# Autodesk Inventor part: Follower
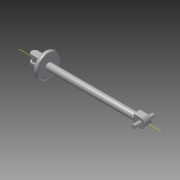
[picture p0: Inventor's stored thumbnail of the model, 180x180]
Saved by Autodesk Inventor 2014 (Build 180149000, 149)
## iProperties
Created: 2008-06
Part Number: Follower
Document SubType Name: Modeling
Designer: tangg
Density: 7.85 g/cm^3
Mass: 2.02034 g
Surface Area: 17.8273 cm^2
Volume: 2.02034 cm^3
Stock Number: Follower
Material: Alloy Steel
Appearance: Steel
Author: tangg
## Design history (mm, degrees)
sketch "Sketch1"
  geometry: L1 (0, 3.75)-(-82.55, 3.75); L2 (-82.55, 3.75)-(-82.55, -3.75); L3 (-82.55, -3.75)-(0, -3.75); L4 (0, -3.75)-(0, 3.75); 2 further points
  constraints: 8 end point, 3 perpendicular, 1 coincident, 1 midpoint, 1 vertical, 1 vertical alignment, 2 other
  dimensions: "d0" = 7.5 distance of L3.end L1.start; "d1" = 82.55 distance of L2.end L3.end
extrude "Extrusion1" new body sketch "Sketch1" stored distance "d2" = 5.08; taper "d3" = 0 deg
workplane "Work Plane4"
sketch "Sketch16"
  geometry: L1 (3.75, 2.54)-(3.75, -2.54) reference; L2 (3.75, -2.54)-(-3.75, -2.54) reference; L3 (-3.75, -2.54)-(-3.75, 2.54) reference; L4 (-3.75, 2.54)-(3.75, 2.54) reference; C1 r 2.54 at (0, 0); 1 further point
  constraints: 1 centre point, 1 coincident
  dimensions: "d28" = 5.08 diameter of C1
extrude "Extrusion11" cut sketch "Sketch16" distance "d29" = 69.85; taper "d30" = 0 deg
sketch "Sketch2"
  geometry: C1 r 1.5 at (0, 0); 1 further point
  constraints: 1 centre point, 1 coincident
  dimensions: "d32" = 3 diameter of C1
extrude "Extrusion2" join sketch "Sketch2" stored distance "d4" = 15.24; taper "d5" = 0 deg
sketch "Sketch11"
  geometry: L1 (82.55, -2.54)-(82.55, 2.54) reference; L2 (82.55, -2.54)-(82.55, 2.54) reference; C1 r 2.54 at (82.55, 0); 2 further points
  constraints: 1 centre point, 1 coincident, 1 midpoint
extrude "Extrusion7" join sketch "Sketch11" stored distance "d18" = 7.5; taper "d19" = 0 deg
sketch "Sketch12"
  geometry: L1 (5.08, -2.54)-(0, -2.54) reference; C1 r 4.763 at (82.55, 0); A1 r 2.54 centre (82.55, 0) between (82.55, -2.54) and (82.55, 2.54) reference; A2 r 2.54 centre (82.55, 0) between (82.55, -2.54) and (82.55, 2.54) reference; 2 further points
  constraints: 1 centre point, 1 coincident
extrude "Extrusion8" cut sketch "Sketch12" stored distance "d20" = 3.81; taper "d21" = 0 deg
sketch "Sketch15"
  geometry: C1 r 1.587 at (82.55, 0); A1 r 2.54 centre (82.55, 0) between (82.55, -2.54) and (82.55, 2.54) reference; 3 further points
  constraints: 1 centre point, 1 coincident
extrude "Extrusion10" join sketch "Sketch15" stored distance "d24" = 5.08; taper "d25" = 0 deg
fillet "Fillet2" dims "d26" = 0.3175
sketch "Sketch17"
  geometry: C1 r 9 at (0, 0); 1 further point
  constraints: 1 centre point, 1 coincident
  dimensions: "d36" = 18 diameter of C1
extrude "Extrusion12" join sketch "Sketch17" distance "d33" = 3; taper "d34" = 0 deg
fillet "Fillet4" dims "d35" = 1
body "Solid1"
node "Projected Loop3"
node "Projected Loop4"
node "Project Cut Edges1"
other parameters: "d27" = -5.08
